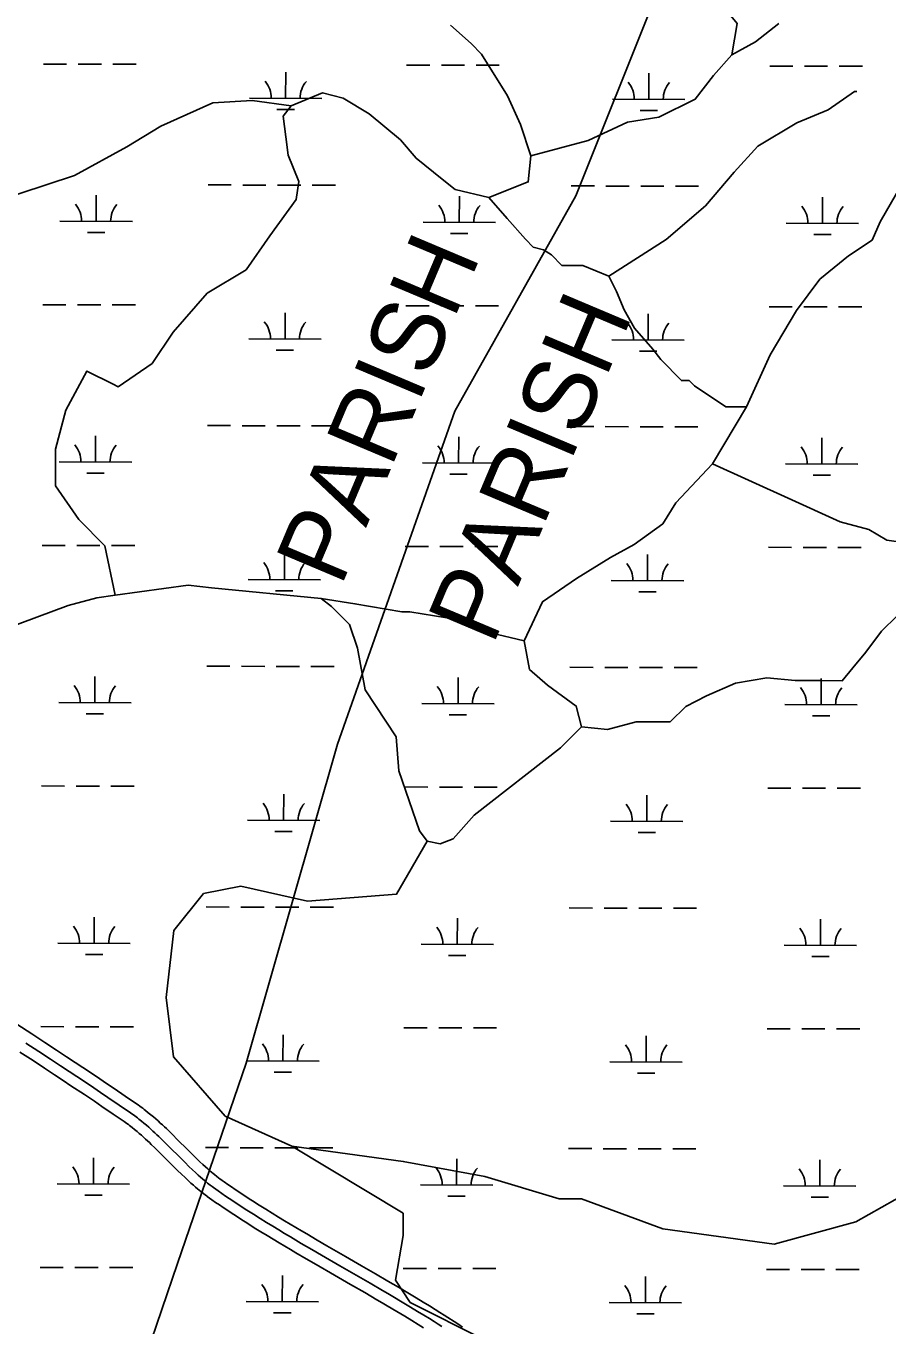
# Model space of a CAD drawing. Extents: x 3161615 to 3199515, y 867541 to 892976.
# Drawn here: x 3178943 to 3180135, y 874884 to 876681 of the extents above; entities that cross this region are included whole.
import ezdxf

# ---------------------------------------------------------------- set-up
doc = ezdxf.new("R2010")
doc.units = 0
for name, color, linetype in [('V-ROAD-CNTR', 7, 'Continuous'), ('V-TOPO-BNDY', 7, 'Continuous'), ('V-TOPO-GNAM-IDEN', 7, 'Continuous'), ('V-TOPO-SHOR', 7, 'Continuous'), ('V-WETL-SWMP', 7, 'Continuous')]:
    doc.layers.add(name, color=color, linetype=linetype)

msp = doc.modelspace()

# ---------------------------------------------------------------- linework, layer by layer
at = {"layer": 'V-ROAD-CNTR'}
for points in [[(3178930.5, 875300.8), (3178951.3, 875287.2), (3178969.5, 875275.4), (3178985.4, 875264.9), (3178999.3, 875255.8), (3179011.5, 875247.7), (3179022.1, 875240.7), (3179040.7, 875228.3), (3179054.6, 875218.9), (3179065, 875211.9), (3179080.5, 875201.3), (3179096.1, 875190.6), (3179098.3, 875189.1), (3179100.5, 875187.6), (3179102.6, 875186), (3179104.6, 875184.5), (3179106.6, 875183), (3179108.6, 875181.4), (3179112.4, 875178.4), (3179116, 875175.5), (3179119.5, 875172.5), (3179122.8, 875169.7), (3179125.9, 875166.9), (3179128.9, 875164.1), (3179131.8, 875161.4), (3179134.6, 875158.8), (3179137.3, 875156.3), (3179142.4, 875151.3), (3179147.1, 875146.7), (3179151.5, 875142.3), (3179167.7, 875126), (3179173.8, 875120), (3179179, 875114.9), (3179183.7, 875110.5), (3179187.8, 875106.7), (3179191.3, 875103.4), (3179194.5, 875100.6), (3179197.3, 875098.2), (3179199.7, 875096.1), (3179201.9, 875094.3), (3179203.7, 875092.8), (3179207.1, 875090.1), (3179209.6, 875088.2), (3179211.6, 875086.7)], [(3178935, 875262.1), (3178953.1, 875250.3), (3178969, 875239.9), (3178982.8, 875230.7), (3178994.9, 875222.7), (3179005.5, 875215.7), (3179024, 875203.4), (3179037.8, 875194.1), (3179048.1, 875187.1), (3179063.6, 875176.5), (3179079, 875166), (3179081, 875164.6), (3179082.9, 875163.2), (3179084.8, 875161.9), (3179086.6, 875160.5), (3179088.4, 875159.2), (3179090.1, 875157.9), (3179093.5, 875155.1), (3179096.8, 875152.4), (3179099.9, 875149.8), (3179103, 875147.1), (3179105.9, 875144.5), (3179108.7, 875142), (3179111.4, 875139.5), (3179114, 875137), (3179116.5, 875134.6), (3179121.4, 875129.9), (3179126, 875125.4), (3179130.3, 875121.1), (3179146.5, 875104.8), (3179152.7, 875098.6), (3179158.2, 875093.3), (3179163.1, 875088.6), (3179167.4, 875084.6), (3179171.3, 875081.1), (3179174.7, 875078), (3179177.8, 875075.4), (3179180.4, 875073.1), (3179182.8, 875071.2), (3179184.9, 875069.4), (3179188.6, 875066.5), (3179191.4, 875064.3), (3179193.5, 875062.8)], [(3178943.2, 875274.7), (3178961.3, 875262.8), (3178977.2, 875252.4), (3178991.1, 875243.3), (3179003.2, 875235.2), (3179013.8, 875228.2), (3179032.3, 875215.8), (3179046.2, 875206.5), (3179056.6, 875199.5), (3179072.1, 875188.9), (3179087.6, 875178.3), (3179089.7, 875176.9), (3179091.7, 875175.4), (3179093.7, 875174), (3179095.6, 875172.5), (3179097.5, 875171.1), (3179099.3, 875169.6), (3179102.9, 875166.8), (3179106.4, 875163.9), (3179109.7, 875161.1), (3179112.9, 875158.4), (3179115.9, 875155.7), (3179118.8, 875153), (3179121.6, 875150.5), (3179124.3, 875147.9), (3179126.9, 875145.4), (3179131.9, 875140.6), (3179136.6, 875136), (3179140.9, 875131.7), (3179157.1, 875115.4), (3179163.2, 875109.3), (3179168.6, 875104.1), (3179173.4, 875099.5), (3179177.6, 875095.6), (3179181.3, 875092.2), (3179184.6, 875089.3), (3179187.5, 875086.8), (3179190.1, 875084.6), (3179192.3, 875082.8), (3179194.3, 875081.1), (3179197.9, 875078.3), (3179200.5, 875076.3), (3179202.6, 875074.8)], [(3179211.4, 875086.9), (3179214.4, 875084.7), (3179217.3, 875082.6), (3179222.4, 875079.1), (3179227.5, 875075.7), (3179232.4, 875072.3), (3179237.4, 875069), (3179242.3, 875065.7), (3179247.1, 875062.6), (3179251.8, 875059.5), (3179256.5, 875056.5), (3179265.8, 875050.5), (3179274.8, 875044.8), (3179283.6, 875039.4), (3179292.1, 875034.1), (3179300.4, 875029.1), (3179308.5, 875024.2), (3179316.3, 875019.5), (3179324, 875015), (3179331.4, 875010.7), (3179345.7, 875002.2), (3179359.2, 874994.4), (3179384.7, 874979.7), (3179407, 874966.9), (3179426.5, 874955.6), (3179443.6, 874945.7), (3179451, 874941.3), (3179458, 874937.2), (3179471.1, 874929.4), (3179482.5, 874922.6), (3179492.4, 874916.5), (3179501.1, 874911.2), (3179508.7, 874906.4), (3179515.3, 874902.3), (3179521.1, 874898.6), (3179526.2, 874895.4), (3179535, 874889.7), (3179541.5, 874885.4), (3179546.5, 874882.1)], [(3179193.7, 875062.6), (3179196.9, 875060.3), (3179200.1, 875058), (3179205.4, 875054.4), (3179210.6, 875050.8), (3179215.7, 875047.4), (3179220.7, 875044), (3179225.7, 875040.7), (3179230.6, 875037.5), (3179235.5, 875034.3), (3179240.3, 875031.2), (3179249.7, 875025.2), (3179258.9, 875019.4), (3179267.8, 875013.9), (3179276.5, 875008.5), (3179284.9, 875003.4), (3179293.1, 874998.5), (3179301, 874993.8), (3179308.7, 874989.2), (3179316.2, 874984.8), (3179330.6, 874976.3), (3179344.2, 874968.4), (3179369.7, 874953.7), (3179392, 874940.9), (3179411.4, 874929.7), (3179428.4, 874919.8), (3179435.8, 874915.5), (3179442.7, 874911.4), (3179455.7, 874903.7), (3179467, 874896.9), (3179476.8, 874890.9), (3179485.3, 874885.7), (3179492.8, 874881)], [(3179202.6, 875074.8), (3179205.6, 875072.5), (3179208.7, 875070.3), (3179213.9, 875066.7), (3179219, 875063.2), (3179224.1, 875059.8), (3179229.1, 875056.5), (3179234, 875053.2), (3179238.9, 875050), (3179243.7, 875046.9), (3179248.4, 875043.8), (3179257.7, 875037.9), (3179266.8, 875032.1), (3179275.7, 875026.6), (3179284.3, 875021.3), (3179292.7, 875016.3), (3179300.8, 875011.4), (3179308.7, 875006.7), (3179316.3, 875002.1), (3179323.8, 874997.7), (3179338.2, 874989.3), (3179351.7, 874981.4), (3179377.2, 874966.7), (3179399.5, 874953.9), (3179419, 874942.7), (3179436, 874932.8), (3179443.4, 874928.4), (3179450.4, 874924.3), (3179463.4, 874916.6), (3179474.7, 874909.7), (3179484.6, 874903.7), (3179493.2, 874898.4), (3179500.8, 874893.7), (3179507.3, 874889.6), (3179513.1, 874886), (3179518.1, 874882.8)]]:
    msp.add_lwpolyline(points, dxfattribs=at)
at = {"layer": 'V-TOPO-BNDY'}
for p, q in [((3179703.3, 876445.8), (3179906.8, 876954.4)), ((3179536.1, 876148.3), (3179703.3, 876445.8)), ((3179373.7, 875687.9), (3179536.1, 876148.3)), ((3179247.4, 875247), (3179373.7, 875687.9)), ((3179152.6, 874969.8), (3179247.4, 875247)), ((3179064.1, 874711.2), (3179152.6, 874969.8))]:
    msp.add_line(p, q, dxfattribs=at)
at = {"layer": 'V-TOPO-SHOR'}
for points in [[(3179918.9, 876640.8), (3179926.3, 876684), (3179908.3, 876705.7), (3179886.7, 876727.3), (3179865.2, 876741.8), (3179840, 876770.7), (3179822, 876788.8), (3179822.1, 876806.8), (3179829.4, 876832), (3179847.5, 876871.6), (3179854.7, 876889.6), (3179854.7, 876886)], [(3179583.2, 876443.5), (3179637.4, 876465), (3179641.1, 876501), (3179626.8, 876544.3), (3179608.9, 876584), (3179573, 876641.7), (3179558.6, 876656.2), (3179529.8, 876681.5)], [(3179641.1, 876501), (3179720.4, 876522.4), (3179774.5, 876547.5), (3179817.8, 876554.6), (3179868.3, 876579.6), (3179893.6, 876612), (3179918.9, 876640.8), (3179951.4, 876658.7), (3179983.9, 876683.8)], [(3179748.7, 876334.9), (3179828.1, 876385.2), (3179882.3, 876431.9), (3179922.1, 876478.6), (3179954.6, 876514.5), (3180008.8, 876546.8), (3180052.1, 876564.7), (3180088.2, 876589.8), (3180091.8, 876589.8)], [(3179309.7, 876570.4), (3179255.7, 876577.7), (3179201.6, 876574.3), (3179129.5, 876542), (3179082.5, 876513.3), (3179010.3, 876473.9), (3178934.6, 876448.9), (3178858.9, 876423.9), (3178793.9, 876391.6), (3178747, 876366.5), (3178700, 876330.6), (3178674.8, 876309.1), (3178620.6, 876266), (3178577.3, 876237.3), (3178512.4, 876233.8), (3178487.2, 876233.9), (3178422.3, 876234.1), (3178382.7, 876237.8), (3178314.2, 876234.4), (3178263.7, 876230.9), (3178224.1, 876223.8), (3178209.6, 876216.7), (3178187.9, 876195.1), (3178162.7, 876169.9)], [(3179066.4, 875893.6), (3179052.2, 875962.1), (3179016.2, 875998.2), (3178983.9, 876045.1), (3178984.1, 876095.6), (3178998.6, 876149.6), (3179027.6, 876203.6), (3179063.6, 876185.5), (3179070.8, 876181.8), (3179117.7, 876214.1), (3179146.7, 876257.3), (3179193.7, 876311.2), (3179247.8, 876343.5), (3179280.4, 876390.3), (3179316.6, 876440.6), (3179320.2, 876465.8), (3179305.9, 876501.9), (3179302.4, 876527.2), (3179298.9, 876556), (3179309.7, 876570.4), (3179353, 876588.3), (3179381.8, 876581), (3179417.8, 876559.3), (3179460.9, 876523.1), (3179482.5, 876497.8), (3179518.4, 876468.9), (3179536.4, 876454.4), (3179583.2, 876443.5), (3179608.4, 876414.6), (3179633.5, 876385.7), (3179644.3, 876374.9), (3179658.7, 876371.2), (3179669.5, 876364), (3179683.9, 876349.5), (3179694.7, 876349.5), (3179712.7, 876349.4), (3179748.7, 876334.9), (3179759.5, 876313.3), (3179770.2, 876288), (3179784.5, 876262.8), (3179809.7, 876233.9), (3179820.5, 876219.4), (3179849.2, 876190.5), (3179860, 876190.5), (3179867.2, 876183.2), (3179910.4, 876154.3), (3179939.2, 876154.2)], [(3178914.9, 875847.1), (3179001.5, 875879.3), (3179041.2, 875890), (3179066.4, 875893.6), (3179167.3, 875907.7), (3179199.8, 875904), (3179351.1, 875889.2), (3179365.5, 875878.3), (3179390.6, 875853), (3179401.3, 875820.6), (3179412, 875762.9), (3179455.1, 875697.9), (3179458.5, 875651), (3179487.1, 875568.1), (3179497.9, 875553.6), (3179515.9, 875550), (3179533.9, 875557.1), (3179562.9, 875589.5), (3179682, 875682.9), (3179711, 875711.6), (3179703.8, 875740.5), (3179664.3, 875769.4), (3179639.1, 875791.1), (3179632, 875830.7), (3179657.4, 875884.7), (3179704.3, 875917), (3179751.2, 875945.7), (3179783.7, 875963.7), (3179823.4, 875992.4), (3179841.5, 876021.2), (3179892.1, 876075.1), (3179939.2, 876154.2), (3179971.8, 876226.2), (3180008, 876287.4), (3180040.6, 876330.5), (3180080.3, 876362.8), (3180112.8, 876384.4), (3180123.7, 876409.6), (3180167.1, 876485.1)], [(3179892.1, 876075.1), (3179996.5, 876027.9), (3180068.5, 875995.3), (3180108.1, 875984.4), (3180133.3, 875969.9), (3180158.5, 875966.2)], [(3179632, 875830.7), (3179585.2, 875841.7), (3179542, 875859.8), (3179473.6, 875870.8), (3179462.7, 875870.9), (3179397.9, 875881.8), (3179351.1, 875889.2)], [(3180147.4, 875865.4), (3180125.7, 875843.8), (3180104, 875815), (3180086, 875793.5), (3180071.5, 875775.5), (3180042.7, 875775.6), (3180006.6, 875775.7), (3179967, 875779.4), (3179923.7, 875772.3), (3179884, 875754.4), (3179855.2, 875740), (3179833.5, 875718.5), (3179808.3, 875718.5), (3179786.6, 875718.6), (3179747, 875707.9), (3179711, 875711.6)], [(3179497.9, 875553.6), (3179455.5, 875480.5), (3179332.4, 875470.6), (3179240.1, 875491.4), (3179188.8, 875481.2), (3179147.6, 875430), (3179137.1, 875337.7), (3179147.1, 875255.6), (3179218.7, 875173.4), (3179310.9, 875132.1), (3179464.8, 875111.1), (3179577.6, 875090.3), (3179680.1, 875059.2), (3179710.9, 875059.1), (3179823.6, 875017.8), (3179977.4, 874996.8), (3180090.4, 875027.3), (3180162.3, 875068.1)], [(3179310.9, 875132.1), (3179464.6, 875039.3), (3179464.5, 875008.5), (3179454.1, 874947), (3179474.5, 874916.1), (3179576.9, 874864.6), (3179679.4, 874813), (3179689.7, 874813), (3179689.6, 874802.7), (3179689.5, 874751.4), (3179607.4, 874741.4)]]:
    msp.add_lwpolyline(points, dxfattribs=at)
at = {"layer": 'V-WETL-SWMP'}
for p, q in [((3178967.5, 876628), (3178999.5, 876627.9)), ((3179015.5, 876627.8), (3179047.5, 876627.8)), ((3179063.5, 876627.7), (3179095.5, 876627.6)), ((3179469.4, 876626.6), (3179501.4, 876626.5)), ((3179517.4, 876626.5), (3179549.4, 876626.4)), ((3179565.4, 876626.3), (3179597.4, 876626.2)), ((3179302.2, 876580.6), (3179302.3, 876616.6)), ((3179804.1, 876579.2), (3179804.2, 876615.2)), ((3179971.3, 876625.2), (3180003.3, 876625.1)), ((3180019.3, 876625.1), (3180051.3, 876625)), ((3180067.3, 876624.9), (3180099.3, 876624.8)), ((3179252.2, 876580.8), (3179352.2, 876580.5)), ((3179754.1, 876579.4), (3179854.1, 876579.1)), ((3179290.2, 876565.2), (3179314.2, 876565.2)), ((3179792.1, 876563.8), (3179816.1, 876563.8)), ((3179040.3, 876410.5), (3179040.4, 876446.5)), ((3179195, 876460.8), (3179227, 876460.8)), ((3179243, 876460.7), (3179275, 876460.6)), ((3179291, 876460.6), (3179323, 876460.5)), ((3179339, 876460.4), (3179371, 876460.4)), ((3179696.9, 876459.5), (3179728.9, 876459.4)), ((3179744.9, 876459.3), (3179776.9, 876459.2)), ((3179792.9, 876459.2), (3179824.9, 876459.1)), ((3179840.9, 876459.1), (3179872.9, 876459)), ((3179542.2, 876409.1), (3179542.3, 876445.1)), ((3180044.1, 876407.8), (3180044.2, 876443.8)), ((3178990.3, 876410.7), (3179090.3, 876410.4)), ((3179028.2, 876395.1), (3179052.2, 876395.1)), ((3179492.2, 876409.3), (3179592.2, 876409)), ((3179530.2, 876393.7), (3179554.2, 876393.7)), ((3179994.1, 876407.9), (3180094.1, 876407.6)), ((3180032.1, 876392.4), (3180056.1, 876392.3)), ((3178966.6, 876295.3), (3178998.6, 876295.2)), ((3179014.6, 876295.2), (3179046.6, 876295.1)), ((3179062.6, 876295), (3179094.6, 876294.9)), ((3179468.5, 876293.9), (3179500.5, 876293.8)), ((3179516.5, 876293.8), (3179548.5, 876293.7)), ((3179564.5, 876293.6), (3179596.5, 876293.6)), ((3179970.4, 876292.5), (3180002.4, 876292.4)), ((3180018.4, 876292.4), (3180050.4, 876292.3)), ((3180066.4, 876292.3), (3180098.4, 876292.2)), ((3179301.3, 876247.9), (3179301.4, 876283.9)), ((3179803.2, 876246.6), (3179803.3, 876282.6)), ((3179251.3, 876248.1), (3179351.3, 876247.8)), ((3179289.2, 876232.5), (3179313.2, 876232.5)), ((3179753.2, 876246.7), (3179853.2, 876246.4)), ((3179791.1, 876231.2), (3179815.1, 876231.1)), ((3179194.1, 876128.2), (3179226.1, 876128.1)), ((3179242.1, 876128), (3179274.1, 876128)), ((3179290.1, 876127.9), (3179322.1, 876127.8)), ((3179338.1, 876127.8), (3179370.1, 876127.7)), ((3179696, 876126.8), (3179728, 876126.7)), ((3179744, 876126.7), (3179776, 876126.6)), ((3179792, 876126.5), (3179824, 876126.4)), ((3179840, 876126.4), (3179872, 876126.3)), ((3179039.4, 876077.9), (3179039.5, 876113.9)), ((3179541.3, 876076.5), (3179541.4, 876112.5)), ((3180043.2, 876075.1), (3180043.3, 876111.1)), ((3178989.4, 876078), (3179089.4, 876077.7)), ((3179491.3, 876076.6), (3179591.3, 876076.3)), ((3179993.2, 876075.2), (3180093.2, 876074.9)), ((3179027.3, 876062.5), (3179051.3, 876062.4)), ((3179529.2, 876061.1), (3179553.2, 876061)), ((3180031.1, 876059.7), (3180055.1, 876059.6)), ((3178965.6, 875962.6), (3178997.6, 875962.5)), ((3179013.6, 875962.5), (3179045.6, 875962.4)), ((3179061.6, 875962.4), (3179093.6, 875962.3)), ((3179467.5, 875961.2), (3179499.5, 875961.2)), ((3179515.5, 875961.1), (3179547.5, 875961)), ((3179563.5, 875961), (3179595.5, 875960.9)), ((3179300.4, 875915.3), (3179300.5, 875951.3)), ((3179802.3, 875913.9), (3179802.4, 875949.9)), ((3179969.5, 875959.9), (3180001.5, 875959.8)), ((3180017.5, 875959.7), (3180049.5, 875959.6)), ((3180065.5, 875959.6), (3180097.5, 875959.5)), ((3179250.4, 875915.4), (3179350.4, 875915.1)), ((3179752.3, 875914), (3179852.3, 875913.7)), ((3179288.3, 875899.9), (3179312.3, 875899.8)), ((3179790.2, 875898.5), (3179814.2, 875898.4)), ((3179038.5, 875745.2), (3179038.6, 875781.2)), ((3179193.2, 875795.5), (3179225.2, 875795.4)), ((3179241.2, 875795.4), (3179273.2, 875795.3)), ((3179289.2, 875795.2), (3179321.2, 875795.1)), ((3179337.2, 875795.1), (3179369.2, 875795)), ((3179695.1, 875794.1), (3179727.1, 875794)), ((3179743.1, 875794), (3179775.1, 875793.9)), ((3179791.1, 875793.8), (3179823.1, 875793.8)), ((3179839.1, 875793.7), (3179871.1, 875793.6)), ((3179540.4, 875743.8), (3179540.5, 875779.8)), ((3180042.3, 875742.4), (3180042.4, 875778.4)), ((3178988.5, 875745.3), (3179088.5, 875745)), ((3179026.4, 875729.8), (3179050.4, 875729.7)), ((3179490.4, 875743.9), (3179590.4, 875743.7)), ((3179528.3, 875728.4), (3179552.3, 875728.3)), ((3179992.3, 875742.5), (3180092.3, 875742.3)), ((3180030.2, 875727), (3180054.2, 875726.9)), ((3178964.7, 875630), (3178996.7, 875629.9)), ((3179012.7, 875629.8), (3179044.7, 875629.7)), ((3179060.7, 875629.7), (3179092.7, 875629.6)), ((3179466.6, 875628.6), (3179498.6, 875628.5)), ((3179514.6, 875628.4), (3179546.6, 875628.3)), ((3179562.6, 875628.3), (3179594.6, 875628.2)), ((3179968.5, 875627.2), (3180000.5, 875627.1)), ((3180016.5, 875627), (3180048.5, 875627)), ((3180064.5, 875626.9), (3180096.5, 875626.8)), ((3179299.4, 875582.6), (3179299.5, 875618.6)), ((3179801.3, 875581.2), (3179801.4, 875617.2)), ((3179249.4, 875582.7), (3179349.4, 875582.5)), ((3179287.4, 875567.2), (3179311.4, 875567.1)), ((3179751.3, 875581.4), (3179851.3, 875581.1)), ((3179789.3, 875565.8), (3179813.3, 875565.7)), ((3179192.3, 875462.8), (3179224.3, 875462.7)), ((3179240.3, 875462.7), (3179272.3, 875462.6)), ((3179288.3, 875462.6), (3179320.3, 875462.5)), ((3179336.3, 875462.4), (3179368.3, 875462.3)), ((3179694.2, 875461.4), (3179726.2, 875461.3)), ((3179742.2, 875461.3), (3179774.2, 875461.2)), ((3179790.2, 875461.2), (3179822.2, 875461.1)), ((3179838.2, 875461), (3179870.2, 875461)), ((3179037.5, 875412.5), (3179037.6, 875448.5)), ((3179539.4, 875411.1), (3179539.5, 875447.1)), ((3180041.3, 875409.7), (3180041.4, 875445.7)), ((3178987.5, 875412.6), (3179087.5, 875412.4)), ((3179489.4, 875411.3), (3179589.4, 875411)), ((3179991.3, 875409.9), (3180091.3, 875409.6)), ((3179025.5, 875397.1), (3179049.5, 875397)), ((3179527.4, 875395.7), (3179551.4, 875395.7)), ((3180029.3, 875394.3), (3180053.3, 875394.3)), ((3178963.8, 875297.3), (3178995.8, 875297.2)), ((3179011.8, 875297.1), (3179043.8, 875297.1)), ((3179059.8, 875297), (3179091.8, 875296.9)), ((3179465.7, 875295.9), (3179497.7, 875295.8)), ((3179298.5, 875249.9), (3179298.6, 875285.9)), ((3179513.7, 875295.8), (3179545.7, 875295.7)), ((3179561.7, 875295.6), (3179593.7, 875295.5)), ((3179800.4, 875248.5), (3179800.5, 875284.5)), ((3179967.6, 875294.5), (3179999.6, 875294.4)), ((3180015.6, 875294.4), (3180047.6, 875294.3)), ((3180063.6, 875294.2), (3180095.6, 875294.2)), ((3179248.5, 875250.1), (3179348.5, 875249.8)), ((3179750.4, 875248.7), (3179850.4, 875248.4)), ((3179286.5, 875234.5), (3179310.5, 875234.5)), ((3179788.4, 875233.1), (3179812.4, 875233.1)), ((3179191.3, 875130.2), (3179223.3, 875130.1)), ((3179239.3, 875130), (3179271.3, 875129.9)), ((3179287.3, 875129.9), (3179319.3, 875129.8)), ((3179335.3, 875129.8), (3179367.3, 875129.7)), ((3179693.2, 875128.8), (3179725.2, 875128.7)), ((3179741.2, 875128.6), (3179773.2, 875128.5)), ((3179789.2, 875128.5), (3179821.2, 875128.4)), ((3179837.2, 875128.4), (3179869.2, 875128.3)), ((3179036.6, 875079.8), (3179036.7, 875115.8)), ((3179538.5, 875078.4), (3179538.6, 875114.4)), ((3180040.4, 875077.1), (3180040.5, 875113.1)), ((3178986.6, 875080), (3179086.6, 875079.7)), ((3179024.6, 875064.4), (3179048.6, 875064.4)), ((3179488.5, 875078.6), (3179588.5, 875078.3)), ((3179526.5, 875063.1), (3179550.5, 875063)), ((3179990.4, 875077.2), (3180090.4, 875076.9)), ((3180028.4, 875061.7), (3180052.4, 875061.6)), ((3178962.9, 874964.6), (3178994.9, 874964.5)), ((3179010.9, 874964.5), (3179042.9, 874964.4)), ((3179058.9, 874964.3), (3179090.9, 874964.3)), ((3179464.8, 874963.2), (3179496.8, 874963.1)), ((3179512.8, 874963.1), (3179544.8, 874963)), ((3179560.8, 874963), (3179592.8, 874962.9)), ((3179966.7, 874961.8), (3179998.7, 874961.7)), ((3180014.7, 874961.7), (3180046.7, 874961.6)), ((3180062.7, 874961.6), (3180094.7, 874961.5)), ((3179297.6, 874917.3), (3179297.7, 874953.3)), ((3179799.5, 874915.9), (3179799.6, 874951.9)), ((3179247.6, 874917.4), (3179347.6, 874917.1)), ((3179285.6, 874901.9), (3179309.6, 874901.8)), ((3179749.5, 874916), (3179849.5, 874915.7)), ((3179787.5, 874900.5), (3179811.5, 874900.4))]:
    msp.add_line(p, q, dxfattribs=at)
for centre, start, end in [((3179247, 876581.2), 359.0699, 40.6135), ((3179357.4, 876580.9), 139.0699, 180.6135), ((3179748.9, 876579.9), 359.0699, 40.6135), ((3179859.3, 876579.6), 139.0699, 180.6135), ((3178985, 876411.2), 359.0699, 40.6135), ((3179095.5, 876410.9), 139.0699, 180.6135), ((3179487, 876409.8), 359.0699, 40.6135), ((3179597.4, 876409.5), 139.0699, 180.6135), ((3179988.9, 876408.4), 359.0699, 40.6135), ((3180099.3, 876408.1), 139.0699, 180.6135), ((3179246, 876248.6), 359.0699, 40.6135), ((3179356.5, 876248.3), 139.0699, 180.6135), ((3179747.9, 876247.2), 359.0699, 40.6135), ((3179858.4, 876246.9), 139.0699, 180.6135), ((3178984.1, 876078.5), 359.0699, 40.6135), ((3179094.6, 876078.2), 139.0699, 180.6135), ((3179486, 876077.1), 359.0699, 40.6135), ((3179596.5, 876076.8), 139.0699, 180.6135), ((3179987.9, 876075.7), 359.0699, 40.6135), ((3180098.4, 876075.4), 139.0699, 180.6135), ((3179245.1, 875915.9), 359.0699, 40.6135), ((3179355.6, 875915.6), 139.0699, 180.6135), ((3179747, 875914.5), 359.0699, 40.6135), ((3179857.5, 875914.2), 139.0699, 180.6135), ((3178983.2, 875745.8), 359.0699, 40.6135), ((3179093.7, 875745.5), 139.0699, 180.6135), ((3179485.1, 875744.4), 359.0699, 40.6135), ((3179595.6, 875744.1), 139.0699, 180.6135), ((3179987, 875743), 359.0699, 40.6135), ((3180097.5, 875742.7), 139.0699, 180.6135), ((3179244.2, 875583.2), 359.0699, 40.6135), ((3179354.7, 875582.9), 139.0699, 180.6135), ((3179746.1, 875581.8), 359.0699, 40.6135), ((3179856.6, 875581.5), 139.0699, 180.6135), ((3178982.3, 875413.1), 359.0699, 40.6135), ((3179092.8, 875412.8), 139.0699, 180.6135), ((3179484.2, 875411.8), 359.0699, 40.6135), ((3179594.7, 875411.4), 139.0699, 180.6135), ((3179986.1, 875410.4), 359.0699, 40.6135), ((3180096.6, 875410.1), 139.0699, 180.6135), ((3179243.3, 875250.6), 359.0699, 40.6135), ((3179353.8, 875250.2), 139.0699, 180.6135), ((3179745.2, 875249.2), 359.0699, 40.6135), ((3179855.7, 875248.9), 139.0699, 180.6135), ((3178981.4, 875080.5), 359.0699, 40.6135), ((3179091.9, 875080.2), 139.0699, 180.6135), ((3179483.3, 875079.1), 359.0699, 40.6135), ((3179593.8, 875078.8), 139.0699, 180.6135), ((3179985.2, 875077.7), 359.0699, 40.6135), ((3180095.7, 875077.4), 139.0699, 180.6135), ((3179242.4, 874917.9), 359.0699, 40.6135), ((3179352.8, 874917.6), 139.0699, 180.6135), ((3179744.3, 874916.5), 359.0699, 40.6135), ((3179854.7, 874916.2), 139.0699, 180.6135)]:
    msp.add_arc(centre, 35.2, start, end, dxfattribs=at)

# ---------------------------------------------------------------- texts
at = {"layer": 'V-TOPO-GNAM-IDEN'}
for p in [(3179378.5, 875904), (3179588.5, 875822.7)]:
    msp.add_text('PARISH', height=100, rotation=67.1193, dxfattribs=at).set_placement(p)

doc.saveas('drawing.dxf')
